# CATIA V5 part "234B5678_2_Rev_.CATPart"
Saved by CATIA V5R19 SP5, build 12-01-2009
Part number: 234B5678-2 - Below Core Laminate
Publications: "Core Layup Surface", "Layup Surface", "aft_trim_surface", "fwd_trim_surface", "web_surface", "reference_plane", "Flange Limit", "EOP Flange", "Flange 1 Intersect", "Flange 2 Intersect", "Rose 1", "Rose 2", "Rose 3", "Rose 4", "Orientation", "Mat"
Material "Plastic": density 1200 kg/m3, Young's modulus 2.2e+09 Pa, Poisson ratio 0.38, thermal expansion 6.84e-05 1/K
Bounding box of the stored display mesh (mm): x 31563.5 to 31910.439, y -11351.044 to -11176.755, z 5292.518 to 5475.468
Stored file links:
  C:\Users\rem1927\Desktop\Current Explicit Composite Demo\234B5678_2_Rev_.CATPart
  C:\Documents and Settings\rem1927\Desktop\Data Exchange\PDES inc\Pilot Demo Files\Dassault Composite Workbench\Catalog_TN.CATMaterial
  C:\Documents and Settings\rem1927\Desktop\PDF Demos\136Z2301-1_rem_surf.CATPart
  C:\Users\rem1927\Desktop\Current Explicit Composite Demo\Catalog_TNA.CATMaterial
  C:\Program Files\Dassault Systemes\B23SP2PRALL\win_b64\startup\materials\Catalog.CATMaterial
  C:\Users\rem1927\Desktop\Current Explicit Composite Demo\234B5678-3 - Above Core Laminate.CATPart
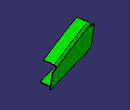
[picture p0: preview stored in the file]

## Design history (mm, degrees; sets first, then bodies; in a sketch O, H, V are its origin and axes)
Parameters
  tool_rad_prmtr = 5.08 mm
  Orientation = 0 deg
  Mat = "Fiberglass Type II"
  `Orientation Name` = "45/-45"
  `Rosette Name` = "Rosette1"
CompParametersFeature1 "Composites Parameters -Ref": Value 0, Value 45
CompStacking1 "Stacking"
AxisSystem1 "Absolute Axis System": origin (0, 0, 0), X (1, 0, 0), Y (0, 1, 0), Z (0, 0, 1)
AxisSystem2 "Rosette 1": origin (31647.2934, -11263.1074, 5379.7103), X (0.9552, 0.2927, -0.0445), Y (0, 0.1502, 0.9887), Z (0.2961, -0.9443, 0.1435)
CompEOPGroupFeature1 "CATCoEOPGroupFeatName"
Set1 "Ref Surfaces"
  DatumSurface1 "aft_trim_surface"
  DatumSurface2 "fwd_trim_surface"
  Plane1 "web_surface": stored without definition
  Plane2 "reference_plane": stored without definition
  DatumSurface3 "Upper Surface"
  DatumSurface4 "Lower Surface"
  Plane3 "Flange Limit": type Offset, RefPlane Plane1, Offset 76.2, reversed
  Plane4 "EOP Flange": type Offset, RefPlane Plane1, Offset 63.5, reversed
  Plane5: type Offset, RefPlane Plane8, Offset 355.6
  Plane6: type Offset, RefPlane Plane8, Offset 127, reversed
  Intersect1: ToIntersect1 Plane1, ToIntersect2 Plane9
  Split1: ToCut Intersect1, Cutting (Plane5; Plane6)
  Extrude1: Element1 Split1, Lim1 127, Lim2 127, Direction Plane9
  Split2: ToCut DatumSurface3, Cutting Plane3
  Split3: ToCut DatumSurface4, Cutting Plane3
  Loft1: Sections (edge of DatumSurface3; edge of DatumSurface4)
  Loft2: Sections (edge of DatumSurface3; edge of DatumSurface4)
  Split4: ToCut Extrude1, Cutting (Split2; Loft1; Split3; Loft2)
  Fillet1: type BiTangent, Element1 Split4, Element2 Split2, Radius 12.7
  Fillet2 "Layup Surface": type BiTangent, Element1 Split3, Element2 Fillet1, Radius 12.7
  Offset1 "Core Layup Surface": Offset Fillet2, Length 4.0183
Set2 "Construction Geometry -Ref"
  Set3 "rosette_construction"
    Intersect2 "Rose 1": ToIntersect1 Plane9, ToIntersect2 Plane8
    Intersect3 "Rose 2": ToIntersect1 Plane8, ToIntersect2 Plane1
    Intersect4 "Rose 3": ToIntersect1 Plane1, ToIntersect2 Plane9
    Intersect5 "Rose 4": ToIntersect1 Intersect4, ToIntersect2 Intersect2
  Set4 "Boundary Construction"
    Intersect6: ToIntersect1 Plane4, ToIntersect2 Plane9
    Split5: ToCut Intersect6, Cutting (Plane5; Plane6)
    Extrude2 "Flange 1 Intersect": Element1 Split5, Lim1 127, Lim2 0, Direction Plane9
    Extrude3 "Flange 2 Intersect": Element1 Split5, Lim1 127, Lim2 0, Direction Plane9
    Intersect7: ToIntersect1 Extrude3, ToIntersect2 Fillet2
    Intersect8: ToIntersect1 Extrude2, ToIntersect2 Fillet2
    Intersect9: ToIntersect1 Fillet2, ToIntersect2 DatumSurface1
    Intersect10: ToIntersect1 Fillet2, ToIntersect2 DatumSurface2
    Corner1: Element1 Intersect10, Element2 Intersect7, Support Fillet2, Radius 6.35
    Corner2: Element1 Corner1, Element2 Intersect9, Support Fillet2, Radius 6.35
    Corner3: Element1 Corner2, Element2 Intersect8, Support Fillet2, Radius 6.35
    Corner4: Element1 Corner3, Element2 Intersect8, Support Fillet2, Radius 6.35
    Split6: ToCut Intersect8, Cutting Corner4
    Join1 "EOP - Eng": Elements (Split6; Corner4)
  Set5 "cutout_construction"
    Plane7: type Offset, RefPlane Plane2, Offset 203.2
    Split7 "Solid Start": ToCut Fillet2, Cutting Join1
  Set6 "Engineering Geometry"
  Set9 "Const 2"
    Plane8: stored without definition
    Plane9: stored without definition
Set10 "Section"
  Plane10: type Offset, RefPlane ZX plane of AxisSystem2, Offset 0
  Plane11: type Offset, RefPlane YZ plane of AxisSystem2, Offset 0
  Plane12: type Offset, RefPlane Plane11, Offset 76.2
  Plane13: type Offset, RefPlane Plane12, Offset 25.4
  Intersect11: ToIntersect1 Plane12, ToIntersect2 Plane10
  Intersect12: ToIntersect1 Plane13, ToIntersect2 Plane10
  Plane14: type Offset, RefPlane XY plane of AxisSystem2, Offset 1.778
  Intersect13: ToIntersect1 Plane14, ToIntersect2 Plane10
  Trim1: Trimmed (Intersect11; Intersect13; Intersect12)
  Plane15: type Offset, RefPlane Plane14, Offset 101.6
  Plane16: type Offset, RefPlane Plane14, Offset 25.4, reversed
  Split8: ToCut Trim1, Cutting (Plane16; Plane15)
  Extrude4: Element1 Split8, Lim1 127, Lim2 127, Direction Plane10
Set11 "Ply Group 1"
  Set12 "Sequence 10"
    Set13 "Ply 10"
      CLDGeom1 "Ply 10 Geometry"
  Set14 "Sequence 20"
    Set15 "Ply 20"
      CLDGeom2 "Ply 20 Geometry"
  Set16 "Sequence 30"
    Set17 "Ply 30"
      CLDGeom3 "Ply 30 Geometry"
  Set18 "Sequence 40"
    Set19 "Ply 40"
      CLDGeom4 "Ply 40 Geometry"
  Set20 "Sequence 50"
    Set21 "Ply 50"
      CLDGeom5 "Ply 50 Geometry"
  Set22 "Sequence 60"
    Set23 "Ply 60"
      CLDGeom6 "Ply 60 Geometry"
  Set24 "Sequence 70"
    Set25 "Ply 70"
      CLDGeom7 "Ply 70 Geometry"
Body1 "234B5678-3" (main body), material "Plastic"
Body2 "Ply 1"
  ThickSurface1: BotOffset 0, Surface Split7, TopOffset 0.254
Body3 "Ply 2"
  ThickSurface2: BotOffset -0.254, Surface Split7, TopOffset 0.508
Body4 "Ply 3"
  ThickSurface3: BotOffset -0.508, Surface Split7, TopOffset 1.5088
Body5 "Ply 4"
  ThickSurface4: BotOffset -1.5088, Surface Split7, TopOffset 2.5095
Body6 "Ply 5"
  ThickSurface5: BotOffset -2.5095, Surface Split7, TopOffset 2.7635
Body7 "Ply 6"
  ThickSurface6: BotOffset -2.7635, Surface Split7, TopOffset 3.0175
Body8 "Ply 7"
  ThickSurface7: BotOffset -3.0175, Surface Split7, TopOffset 4.0183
